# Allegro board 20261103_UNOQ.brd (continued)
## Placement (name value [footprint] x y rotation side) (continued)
R2645  0  [R0201_H030]  46.38 46.96 270 bottom
R2646  0  [R0201_H030]  20.19 4.31 90 bottom
R2660  220K  [R0201_H030]  33.71 57.35 90 top
R2661  220K  [R0201_H030]  32.61 57.35 270 top
R2664  220K  [R0201_H030]  43.45 60.86 0 top
R2665  220K  [R0201_H030]  44.25 60.86 0 top
R2666  2.2K  [R0201_H030]  33.53 13.54 270 bottom
R2667  2.2K  [R0201_H030]  35.57 13.54 270 bottom
R2668  0  [R0201_H030]  36.6 13.54 270 bottom
R2669  0  [R0201_H030]  34.55 13.54 270 bottom
R2670  0  [R0201_H030]  45.11 18.68 90 top
R2671  0  [R0201_H030]  45.14 18.14 90 top
R2701  10_1%  [R0402_H040]  21.85 8.44 180 top
R2702  10_1%  [R0402_H040]  20.89 8.47 180 top
R2703  10_1%  [R0402_H040]  19.95 8.47 180 top
R2704  10_1%  [R0402_H040]  17.21 8.46 180 top
R2705  10_1%  [R0402_H040]  18.08 8.47 180 top
R2706  10_1%  [R0402_H040]  7.87 8.24 180 top
R2707  10_1%  [R0402_H040]  11.34 8.24 180 top
R2708  10_1%  [R0402_H040]  10.48 8.26 180 top
R2709  10_1%  [R0402_H040]  9.55 8.26 180 top
R2710  10_1%  [R0402_H040]  8.69 8.25 180 top
R2711  10_1%  [R0402_H040]  19.03 8.47 180 top
R2712  1K  [R0201_H030]  42.2 32.8 180 bottom
R2713  1K  [R0201_H030]  45.4 33.4 90 bottom
R2714  1K  [R0201_H030]  41.5 34.2 180 bottom
R2715  1K  [R0201_H030]  40.1 35.4 90 bottom
R2716  1K  [R0201_H030]  39.1 31.6 180 bottom
R2717  1K  [R0201_H030]  41.6 31.7 180 bottom
R2723  4.7K  [R0402_H040]  46.56 5.34 0 bottom
R2724  15K_1%  [R0402_H040]  45.64 5.34 0 bottom
R2725  4.7K  [R0402_H040]  41.95 5.34 0 bottom
R2726  4.7K  [R0402_H040]  42.87 5.34 0 bottom
R2727  15K_1%  [R0402_H040]  44.72 5.34 0 bottom
R2728  4.7K  [R0402_H040]  43.8 5.34 0 bottom
R2729  4.7K  [R0402_H040]  39.11 5.76 0 bottom
R2730  15K_1%  [R0402_H040]  37.79 6.25 90 bottom
R2731  4.7K  [R0402_H040]  35.85 6.44 90 bottom
R2732  4.7K  [R0402_H040]  41.03 5.34 0 bottom
R2733  15K_1%  [R0402_H040]  40.18 5.84 0 bottom
R2734  4.7K  [R0402_H040]  39.7 4.43 90 bottom
R2735  330  [R0402_H040]  29.21 65.49 90 top
R2801  10K_1%  [R0201_H030]  11.94 40.04 90 bottom
R2802  499K_1%  [R0201_H030]  13.33 39.75 0 bottom
R2803  95.3K_1%  [R0201_H030]  12.83 39.75 180 bottom
R2804  10K_1%  [R0201_H030]  10.75 32.15 90 bottom
R2805  453K_1%  [R0201_H030]  11.6 31.18 0 bottom
R2806  100K  [R0201_H030]  11.98 32.07 90 bottom
R2807  0  [R1206_H080]  7.7 41.5 180 bottom
R2808  10K_1%  [R0201_H030]  15.37 42.32 90 bottom
R2809  10K_1%  [R0201_H030]  14.22 46.58 270 bottom
R2810  10K_1%  [R0201_H030]  17.19 41.62 0 bottom
R2811  301K_1%  [R0201_H030]  5.72 43.02 180 top
R2812  100K  [R0201_H030]  5.72 44.16 180 top
R2813  0  [R0201_H030]  9.2 45.16 270 top
R2814  100K  [R0201_H030]  6.92 45.23 270 top
R2815  19.1K_1%  [R0201_H030]  5.58 45.54 180 top
R2816  1K  [R0201_H030]  6.93 45.84 270 top
R2817  0  [R0603_H060]  8.9 31.84 90 bottom
R2901  0  [R0201_H030]  23.73 62.55 270 top
R2902  0  [R0201_H030]  3.78 60.94 90 top
R2903  0  [R0201_H030]  5.59 49.44 180 top
R2904  0  [R0201_H030]  4.38 63.34 90 top
R2905  0  [R0201_H030]  4.38 62.6 90 top
R2906  0  [R0201_H030]  4.65 60.65 180 top
R2908  0  [R0201_H030]  23.19 59.79 180 top
R2909  0  [R0201_H030]  3.28 61.77 90 top
R3001  1M  [R0201_H030]  33.83 49.61 0 top
R3002  1M  [R0201_H030]  34.8 49.86 90 top
R3003  0  [R0201_H030]  34.93 58.27 0 top
R3004  0  [R0201_H030]  36.79 57.76 180 top
R3005  0  [R0201_H030]  37.56 57.76 180 top
R3006  0  [R0201_H030]  38.77 59.19 270 top
R3007  1M  [R0201_H030]  33.07 53.8 0 top
R3009  0  [R0402_H040]  39.05 51.38 0 bottom
R3010  0  [R0402_H040]  33.64 46.39 270 top
R3011  0  [R0402_H040]  36.75 46.82 270 top
R3012  0  [R0402_H040]  36.87 50.75 90 bottom
R3013  0  [R0402_H040]  31.52 51.16 90 top
R3014  0  [R0201_H030]  34.67 43.78 90 top
R3015  0  [R0201_H030]  31.24 43.78 270 top
R3016  0  [R0201_H030]  37.14 43.17 180 top
R3017  0  [R0201_H030]  37.79 43.04 180 top
R3018  0  [R0201_H030]  36.55 43.34 180 top
R3019  39.2K_1%  [R0201_H030]  32.97 50.67 90 top
R3020  5.6K_1%  [R0201_H030]  32.97 51.21 270 top
R3022  2.2K  [R0201_H030]  35.85 52.15 90 bottom
R3023  2.2K  [R0201_H030]  38.96 54.61 270 top
R3024  10K_1%  [R0201_H030]  25.7 61.09 0 top
R3025  4.7K  [R0201_H030]  38.96 54.05 270 top
R3026  2.2K  [R0201_H030]  32.29 43.77 270 top
R3027  2.2K  [R0201_H030]  33.49 43.77 90 top
R3028  0  [R0201_H030]  35.37 41.73 270 top
RT701  NCP03WF104F05RL  [TRES0201_H030]  39.24 14.53 90 bottom
RT1901  NCP03WF104F05RL  [TRES0201_H030]  41.96 10.31 0 top
SB701  SB2P  [SB0201]  36.19 15.44 180 top
SB1001  SB2P  [SB0201]  30.75 20.04 90 top
SB1002  SB2P  [SB0201]  30.78 19.52 90 top
SB1003  SB2P  [SB0201]  29.99 17.62 90 top
SB1004  SB2P  [SB0201]  29.99 18.13 90 top
SB1701  SB2P  [SB0201]  26.99 29.02 0 top
SB1702  SB2P  [SB0201]  26.44 29.02 0 top
SB1801  SB2P  [SB0201]  26.75 38.85 0 top
SB1802  SB2P  [SB0201]  26.3 38.85 0 top
SB2801  SB2P  [SB0201#2]  11.97 39.19 90 bottom
SOC1  QRB-2210-0-NSP752-TR-00-0  [BGA752_120X124_0D4_H10]  29.77 34.28 90 top
TP601  TP  [TP20MIL]  38.94 8.88 0 top
TP602  TP  [TP20MIL]  38.23 8.85 0 top
TP701  TP  [TP20MIL]  31.4 12.87 0 top
TP702  TP  [TP20MIL]  29.34 11.65 0 top
TP703  TP  [TP20MIL]  39.66 8.85 0 top
TP704  TP  [TP20MIL]  37.62 9.87 0 top
TP705  TP  [TP20MIL]  30.09 14.96 0 top
TP706  TP  [TP20MIL]  35.79 9.22 0 top
TP1203  TP  [TP20MIL]  32.16 24.81 0 top
TP1204  TP  [TP20MIL]  32.16 25.61 0 top
TP1205  TP  [TP20MIL]  31.33 25.58 0 top
TP1206  TP  [TP20MIL]  31.33 24.78 0 top
TP1207  TP  [TP32MIL_OSP]  10.67 2.17 180 bottom
TP1208  TP  [TP32MIL_OSP]  12.67 2.17 180 bottom
TP1209  TP  [TP32MIL_OSP]  14.67 2.17 180 bottom
TP1210  TP  [TP32MIL_OSP]  16.67 2.17 180 bottom
TP1211  TP  [TP32MIL_OSP]  18.67 2.17 180 bottom
TP1212  TP  [TP32MIL_OSP]  20.67 2.17 180 bottom
TP1213  TP  [TP32MIL_OSP]  22.67 2.17 180 bottom
TP1301  TP  [TP20MIL]  35.26 23.17 0 top
TP1310  TP  [TP20MIL]  22.99 35.86 90 top
TP1311  TP  [TP20MIL]  22.45 33.93 90 top
TP1313  TP  [TP20MIL]  22.94 34.55 90 top
TP1314  TP  [TP20MIL]  22.52 35.24 90 top
TP1315  TP  [TP20MIL]  22.51 36.56 0 top
TP1501  TP  [TP20MIL]  30.04 25.32 0 top
TP1502  TP  [TP20MIL]  30.04 26.07 0 top
TP2501  TP  [TP20MIL]  17.4 26.67 0 bottom
TP2502  TP  [TP20MIL]  18.56 38.02 270 bottom
TP2503  TP  [TP20MIL]  17.4 25.91 0 bottom
TP2504  TP  [TP20MIL]  17.7 24.13 270 bottom
TP2506  TP  [TP20MIL]  7.41 23.08 270 bottom
TP2602  TP  [TP20MIL]  6.65 36.94 180 bottom
TP2603  TP  [TP20MIL]  6.31 42.62 180 bottom
TP2610  TP  [TP32MIL_OSP]  23.6 33.26 180 bottom
TP2611  TP  [TP32MIL_OSP]  51.5 55.75 180 bottom
TP2612  TP  [TP32MIL_OSP]  36.52 67.05 180 bottom
TP2613  TP  [TP32MIL_OSP]  38.52 67.05 180 bottom
TP2614  TP  [TP32MIL_OSP]  49.37 59.75 180 bottom
TP2615  TP  [TP40MIL]  49.37 55.75 180 bottom
TP2616  TP  [TP40MIL]  49.37 57.75 180 bottom
TP2617  TP  [TP32MIL_OSP]  51.5 59.75 180 bottom
TP2618  TP  [TP32MIL_OSP]  51.5 57.75 180 bottom
TP2901  TP  [TP20MIL]  4.31 51.11 0 top
TP3001  TP  [TP20MIL]  16.17 50.9 180 bottom
TP3002  TP  [TP20MIL]  35.55 43.82 0 top
TP3003  TP  [TP20MIL]  30.99 44.43 0 top
TP3004  TP  [TP20MIL]  37.58 56.91 0 top
TP3005  TP  [TP20MIL]  39.03 58.58 0 top
TP3006  TP  [TP20MIL]  38.53 55.32 0 top
TP3007  TP  [TP20MIL]  33.15 52.07 0 top
U1101  TXS0104ERUTR_QFN12P  [QFN12P_20X17_04_H060]  16.75 38.12 180 bottom
U1102  TXS0101DBVR_SOT23_6P  [SOT23_6P_29X28_H150]  17.09 32.69 90 bottom
U2501  74LVC1G3157DW-7_SOT363_6P  [SOT363_6P_21X20_H110]  44.71 44.01 270 bottom
U2601  RCLAMP0524PATCT  [DFN10P_25X10_05_H070_SE]  30.95 60.45 180 top
U2602  RCLAMP0524PATCT  [DFN10P_25X10_05_H070_SE]  36.73 59.33 270 top
U2604  RCLAMP3654PATCT_DFN6P  [DFN6P_16_PAD13X05_05H070P13X045]  40.64 58.45 90 top
U2605  RCLAMP0524PATCT  [DFN10P_25X10_05_H070_SE]  14.62 61.22 90 bottom
U2606  RCLAMP0524PATCT  [DFN10P_25X10_05_H070_SE]  33.63 52.68 270 bottom
U2607  RCLAMP0522P.TCT  [DFN6P_16X10_05_H070]  20.44 61.22 90 bottom
U2608  RCLAMP0524PATCT  [DFN10P_25X10_05_H070_SE]  26.05 62.12 90 bottom
U2609  RCLAMP0524PATCT  [DFN10P_25X10_05_H070_SE]  18.39 52.68 270 bottom
U2610  RCLAMP0524PATCT  [DFN10P_25X10_05_H070_SE]  26.01 52.68 270 bottom
U2611  RCLAMP0524PATCT  [DFN10P_25X10_05_H070_SE]  41.86 49.7 0 bottom
U2612  RCLAMP0524PATCT  [DFN10P_25X10_05_H070_SE]  41.3 52.58 270 bottom
U2801  TPS62A02APDDCR_SOT23_6P  [SOT23_6P_29X28_H110]  12.92 42.03 180 bottom
U2802  TPS62A02APDDCR_SOT23_6P  [SOT23_6P_29X28_H110]  11.74 34.1 180 bottom
U2803  LMR51440SDRRR_DFN12P  [DFN12_30_0D5_H08_P25X13_DRR]  8.05 43.04 0 top
U2901  WCBN3536A_MODULE51P  [MODULE51_160X120_1D1_H26_LITEON]  13.86 57.13 90 top
U3001  ANX7625BN-AC-R_BGA64P  [BGA64P_40_04_H090]  35.97 52.54 180 top
U3004  TPS7A2030PDBVR_SOT23_5P  [SOT23_5P_29X28_H150]  26.65 58.48 270 top
Y701  38.4M_X1.6X1.2  [XTAL4P_16X12_H070_TXC]  33.07 10.79 180 top
Y2501  16M_X3.2X2.5  [XTAL4P_32X25_H080]  10.36 17.19 270 bottom
Y2502  32.768K_X3.2X1.5  [XTAL2P_32X15_H090]  14.96 16.87 270 bottom
Y3001  27M_X3.2X2.5  [XTAL4P_32X25_H080_HOSONIC]  30.05 53.73 270 top

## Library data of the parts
ANT1 = CLIP2P
C501-C514 C601-C610 C701-C721 C801-C832 C901 C902 C1001-C1012 C1101-C1106 C1201-C1203 C1601-C1604 C1701-C1725 C1727-C1743 C1801-C1831 C1833-C1851 C1901-C1940 C2101-C2107 C2201-C2220 C2501-C2529 C2601-C2605 C2607-C2611 C2614-C2633 C2701-C2706 C2801-C2816 C2901 C2907 C2909 C2911 C2912 C2921-C2924 C3001-C3018 C3021 C3022 C3025-C3028 = CAP_NP
C3019 C3020 = CAP_NP: signal model: CAP_NP_78.10423.L15_C0201_H030__100NF/10V
D2801-D2803 = DIODE_SCHOTTKY
D26001-D26003 D26005-D26009 D26017 D26046-D26051 D26063-D26067 D26069-D26076 D26087-D26094 D26097 D26099-D26105 = DIODE_ESD_BI
D26201 = PJGBLC24C_SOD323FL
D27001-D27104 D27201 = LED
D27301 D27302 D27401 D27402 = LED4P_RED_BLU_GRN_A1
DRAM1 = MT53E512M32D1ZW-046_WT_B
EMMC1 = EMMC16G-MW28-GA01_BGA153P
F501 = BEAD
JANALOG1 = WTB14P_NP2P_0
JBTN1 = TS-A57AHNP-2-W-S085_SW5P
JCTL1 = HEAD2X5P
JDIGITAL1 = HEAD20P_1
JMEDIA1 JMISC1 = HEAD2X30P_F_R
JSPI1 = HEAD2X3P_M
JUSB1 = USB3-24CSW-R9H-H_USB2X12P
L601 L2801 L2802 = L
L1001-L1004 L2803 = CHOKE
MCU1 = STM32U585AII6TR_BGA169P_2
PMIC1 = PM-4125-3-NSP194-TR-01-0_11
Q2707-Q2709 = NPNX2_E2B2C1E1B1C2
Q2801 = PMOSFET_GSD
Q2802 = NPN_BEC
QWIIC1 = WTB4P_NP2P
R501-R503 R601 R603-R607 R701-R703 R705-R709 R901 R902 R1101 R1102 R1201-R1206 R1208 R1301-R1321 R1401 R1522 R1601 R1602 R2113 R2114 R2201 R2202 R2501-R2509 R2511-R2517 R2605-R2619 R2621-R2626 R2631-R2646 R2660 R2661 R2664-R2671 R2701-R2717 R2723-R2735 R2801-R2817 R2901-R2906 R2908 R2909 R3001-R3007 R3009-R3020 R3022-R3028 = RES
R1207 = RES: signal model: RES_63.22038.1F1_R0201_H030_22__22
R1501-R1510 = RES: signal model: RES_DNP_63.R0038.1F1_R0201_H030_0
RT701 RT1901 = TRES
SB701 SB1001-SB1004 SB1701 SB1702 SB1801 SB1802 SB2801 = SB2P
SOC1 = QRB-2210-0-NSP752-TR-00-0_43
TP601 TP602 TP701-TP706 TP1203-TP1213 TP1301 TP1310 TP1311 TP1313-TP1315 TP1501 TP1502 TP2501-TP2504 TP2506 TP2602 TP2603 TP2610-TP2618 TP2901 TP3001-TP3007 = TP
U1101 = TXS0104ERUTR_QFN12P
U1102 = TXS0101DBVR_SOT23_6P
U2501 = 74LVC1G3157DW-7_SOT363_1
U2601 U2602 U2605 U2606 U2608-U2612 = RCLAMP0524PATCT_DFN10P
U2604 = RCLAMP3654PATCT_DFN6P
U2607 = RCLAMP0522P.TCT_DFN6P
U2801 U2802 = TPS62A02APDDCR_SOT23_6P
U2803 = LMR51440SDRRR_DFN12P_1
U2901 = WCBN3536A_MODULE51P
U3001 = ANX7625BN-AC-R_BGA64P
U3004 = TPS7A2030PDBVR_SOT23_5P
Y701 = OW38470002_XTAL4P
Y2501 Y3001 = XTAL4P_P13
Y2502 = XTAL

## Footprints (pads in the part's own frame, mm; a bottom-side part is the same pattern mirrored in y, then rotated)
ANT2_1920X400_A
  rect 1x0.5 smd: 1(0,0)
  custom 1x1 smd: 2(-5.6,-0.25)
BEAD0402_H060
  rect 0.559x0.559 smd: 1(0,0.483) 2(0,-0.483)
BGA64P_40_04_H090
  round 0.25 smd: A1(1.4,-1.4) A2(1,-1.4) A3(0.6,-1.4) A4(0.2,-1.4) A5(-0.2,-1.4) A6(-0.6,-1.4) A7(-1,-1.4) A8(-1.4,-1.4) B1(1.4,-1) B2(1,-1) B3(0.6,-1) B4(0.2,-1) B5(-0.2,-1) B6(-0.6,-1) B7(-1,-1) B8(-1.4,-1) C1(1.4,-0.6) C2(1,-0.6) C3(0.6,-0.6) C4(0.2,-0.6) C5(-0.2,-0.6) C6(-0.6,-0.6) C7(-1,-0.6) C8(-1.4,-0.6) D1(1.4,-0.2) D2(1,-0.2) D3(0.6,-0.2) D4(0.2,-0.2) D5(-0.2,-0.2) D6(-0.6,-0.2) D7(-1,-0.2) D8(-1.4,-0.2) E1(1.4,0.2) E2(1,0.2) E3(0.6,0.2) E4(0.2,0.2) E5(-0.2,0.2) E6(-0.6,0.2) E7(-1,0.2) E8(-1.4,0.2) F1(1.4,0.6) F2(1,0.6) F3(0.6,0.6) F4(0.2,0.6) F5(-0.2,0.6) F6(-0.6,0.6) F7(-1,0.6) F8(-1.4,0.6) G1(1.4,1) G2(1,1) G3(0.6,1) G4(0.2,1) G5(-0.2,1) G6(-0.6,1) G7(-1,1) G8(-1.4,1) H1(1.4,1.4) H2(1,1.4) H3(0.6,1.4) H4(0.2,1.4) H5(-0.2,1.4) H6(-0.6,1.4) H7(-1,1.4) H8(-1.4,1.4)
BGA153P_130X115_05_H090
  round 0.25 smd: A1(3.25,-3.25) A2(2.75,-3.25) A3(2.25,-3.25) A4(1.75,-3.25) A5(1.25,-3.25) A6(0.75,-3.25) A7(0.25,-3.25) A8(-0.25,-3.25) A9(-0.75,-3.25) A10(-1.25,-3.25) A11(-1.75,-3.25) A12(-2.25,-3.25) A13(-2.75,-3.25) A14(-3.25,-3.25) B1(3.25,-2.75) B2(2.75,-2.75) B3(2.25,-2.75) B4(1.75,-2.75) B5(1.25,-2.75) B6(0.75,-2.75) B7(0.25,-2.75) B8(-0.25,-2.75) B9(-0.75,-2.75) B10(-1.25,-2.75) B11(-1.75,-2.75) B12(-2.25,-2.75) B13(-2.75,-2.75) B14(-3.25,-2.75) C1(3.25,-2.25) C2(2.75,-2.25) C3(2.25,-2.25) C4(1.75,-2.25) C5(1.25,-2.25) C6(0.75,-2.25) C7(0.25,-2.25) C8(-0.25,-2.25) C9(-0.75,-2.25) C10(-1.25,-2.25) C11(-1.75,-2.25) C12(-2.25,-2.25) C13(-2.75,-2.25) C14(-3.25,-2.25) D1(3.25,-1.75) D2(2.75,-1.75) D3(2.25,-1.75) D4(1.75,-1.75) D12(-2.25,-1.75) D13(-2.75,-1.75) D14(-3.25,-1.75) E1(3.25,-1.25) E2(2.75,-1.25) E3(2.25,-1.25) E5(1.25,-1.25) E6(0.75,-1.25) E7(0.25,-1.25) E8(-0.25,-1.25) E9(-0.75,-1.25) E10(-1.25,-1.25) E12(-2.25,-1.25) E13(-2.75,-1.25) E14(-3.25,-1.25) F1(3.25,-0.75) F2(2.75,-0.75) F3(2.25,-0.75) F5(1.25,-0.75) F10(-1.25,-0.75) F12(-2.25,-0.75) F13(-2.75,-0.75) F14(-3.25,-0.75) G1(3.25,-0.25) G2(2.75,-0.25) G3(2.25,-0.25) G5(1.25,-0.25) G10(-1.25,-0.25) G12(-2.25,-0.25) G13(-2.75,-0.25) G14(-3.25,-0.25) H1(3.25,0.25) H2(2.75,0.25) H3(2.25,0.25) H5(1.25,0.25) H10(-1.25,0.25) H12(-2.25,0.25) H13(-2.75,0.25) H14(-3.25,0.25) J1(3.25,0.75) J2(2.75,0.75) J3(2.25,0.75) J5(1.25,0.75) J10(-1.25,0.75) J12(-2.25,0.75) J13(-2.75,0.75) J14(-3.25,0.75) K1(3.25,1.25) K2(2.75,1.25) K3(2.25,1.25) K5(1.25,1.25) K6(0.75,1.25) K7(0.25,1.25) K8(-0.25,1.25) K9(-0.75,1.25) K10(-1.25,1.25) K12(-2.25,1.25) K13(-2.75,1.25) K14(-3.25,1.25) L1(3.25,1.75) L2(2.75,1.75) L3(2.25,1.75) L12(-2.25,1.75) L13(-2.75,1.75) L14(-3.25,1.75) M1(3.25,2.25) M2(2.75,2.25) M3(2.25,2.25) M4(1.75,2.25) M5(1.25,2.25) M6(0.75,2.25) M7(0.25,2.25) M8(-0.25,2.25) M9(-0.75,2.25) M10(-1.25,2.25) M11(-1.75,2.25) M12(-2.25,2.25) M13(-2.75,2.25) M14(-3.25,2.25) N1(3.25,2.75) N2(2.75,2.75) N3(2.25,2.75) N4(1.75,2.75) N5(1.25,2.75) N6(0.75,2.75) N7(0.25,2.75) N8(-0.25,2.75) N9(-0.75,2.75) N10(-1.25,2.75) N11(-1.75,2.75) N12(-2.25,2.75) N13(-2.75,2.75) N14(-3.25,2.75) P1(3.25,3.25) P2(2.75,3.25) P3(2.25,3.25) P4(1.75,3.25) P5(1.25,3.25) P6(0.75,3.25) P7(0.25,3.25) P8(-0.25,3.25) P9(-0.75,3.25) P10(-1.25,3.25) P11(-1.75,3.25) P12(-2.25,3.25) P13(-2.75,3.25) P14(-3.25,3.25)
BGA169_70_0D5_H06
  round 0.25 smd: A1(3,-3) A2(2.5,-3) A3(2,-3) A4(1.5,-3) A5(1,-3) A6(0.5,-3) A7(0,-3) A8(-0.5,-3) A9(-1,-3) A10(-1.5,-3) A11(-2,-3) A12(-2.5,-3) A13(-3,-3) B1(3,-2.5) B2(2.5,-2.5) B3(2,-2.5) B4(1.5,-2.5) B5(1,-2.5) B6(0.5,-2.5) B7(0,-2.5) B8(-0.5,-2.5) B9(-1,-2.5) B10(-1.5,-2.5) B11(-2,-2.5) B12(-2.5,-2.5) B13(-3,-2.5) C1(3,-2) C2(2.5,-2) C3(2,-2) C4(1.5,-2) C5(1,-2) C6(0.5,-2) C7(0,-2) C8(-0.5,-2) C9(-1,-2) C10(-1.5,-2) C11(-2,-2) C12(-2.5,-2) C13(-3,-2) D1(3,-1.5) D2(2.5,-1.5) D3(2,-1.5) D4(1.5,-1.5) D5(1,-1.5) D6(0.5,-1.5) D7(0,-1.5) D8(-0.5,-1.5) D9(-1,-1.5) D10(-1.5,-1.5) D11(-2,-1.5) D12(-2.5,-1.5) D13(-3,-1.5) E1(3,-1) E2(2.5,-1) E3(2,-1) E4(1.5,-1) E5(1,-1) E6(0.5,-1) E7(0,-1) E8(-0.5,-1) E9(-1,-1) E10(-1.5,-1) E11(-2,-1) E12(-2.5,-1) E13(-3,-1) F1(3,-0.5) F2(2.5,-0.5) F3(2,-0.5) F4(1.5,-0.5) F5(1,-0.5) F6(0.5,-0.5) F7(0,-0.5) F8(-0.5,-0.5) F9(-1,-0.5) F10(-1.5,-0.5) F11(-2,-0.5) F12(-2.5,-0.5) F13(-3,-0.5) G1(3,0) G2(2.5,0) G3(2,0) G4(1.5,0) G5(1,0) G6(0.5,0) G7(0,0) G8(-0.5,0) G9(-1,0) G10(-1.5,0) G11(-2,0) G12(-2.5,0) G13(-3,0) H1(3,0.5) H2(2.5,0.5) H3(2,0.5) H4(1.5,0.5) H5(1,0.5) H6(0.5,0.5) H7(0,0.5) H8(-0.5,0.5) H9(-1,0.5) H10(-1.5,0.5) H11(-2,0.5) H12(-2.5,0.5) H13(-3,0.5) J1(3,1) J2(2.5,1) J3(2,1) J4(1.5,1) J5(1,1) J6(0.5,1) J7(0,1) J8(-0.5,1) J9(-1,1) J10(-1.5,1) J11(-2,1) J12(-2.5,1) J13(-3,1) K1(3,1.5) K2(2.5,1.5) K3(2,1.5) K4(1.5,1.5) K5(1,1.5) K6(0.5,1.5) K7(0,1.5) K8(-0.5,1.5) K9(-1,1.5) K10(-1.5,1.5) K11(-2,1.5) K12(-2.5,1.5) K13(-3,1.5) L1(3,2) L2(2.5,2) L3(2,2) L4(1.5,2) L5(1,2) L6(0.5,2) L7(0,2) L8(-0.5,2) L9(-1,2) L10(-1.5,2) L11(-2,2) L12(-2.5,2) L13(-3,2) M1(3,2.5) M2(2.5,2.5) M3(2,2.5) M4(1.5,2.5) M5(1,2.5) M6(0.5,2.5) M7(0,2.5) M8(-0.5,2.5) M9(-1,2.5) M10(-1.5,2.5) M11(-2,2.5) M12(-2.5,2.5) M13(-3,2.5) N1(3,3) N2(2.5,3) N3(2,3) N4(1.5,3) N5(1,3) N6(0.5,3) N7(0,3) N8(-0.5,3) N9(-1,3) N10(-1.5,3) N11(-2,3) N12(-2.5,3) N13(-3,3)
BGA194_67X83_0D566_H10_QUALCOMM
  round 0.25 smd: A1(3.679,-2.689) A3(3.113,-2.689) A5(2.547,-2.689) A7(1.981,-2.689) A11(0.849,-2.689) A13(0.283,-2.689) A15(-0.283,-2.689) A17(-0.849,-2.689) A19(-1.415,-2.689) A21(-1.981,-2.689) A23(-2.547,-2.689) A25(-3.113,-2.689) A27(-3.679,-2.689) B2(3.396,-2.405) B4(2.83,-2.405) B6(2.264,-2.405) B8(1.698,-2.405) B12(0.566,-2.405) B14(0,-2.405) B16(-0.566,-2.405) B18(-1.132,-2.405) B22(-2.264,-2.405) B24(-2.83,-2.405) B26(-3.396,-2.405) C1(3.679,-2.122) C3(3.113,-2.122) C5(2.547,-2.122) C7(1.981,-2.122) C11(0.849,-2.122) C13(0.283,-2.122) C17(-0.849,-2.122) C19(-1.415,-2.122) C21(-1.981,-2.122) C23(-2.547,-2.122) C25(-3.113,-2.122) C27(-3.679,-2.122) D2(3.396,-1.839) D4(2.83,-1.839) D6(2.264,-1.839) D8(1.698,-1.839) D10(1.132,-1.839) D12(0.566,-1.839) D22(-2.264,-1.839) D24(-2.83,-1.839) D26(-3.396,-1.839) E1(3.679,-1.556) E3(3.113,-1.556) E5(2.547,-1.556) E7(1.981,-1.556) E9(1.415,-1.556) E11(0.849,-1.556) E15(-0.283,-1.556) E19(-1.415,-1.556) E21(-1.981,-1.556) E23(-2.547,-1.556) E27(-3.679,-1.556) F2(3.396,-1.274) F4(2.83,-1.274) F6(2.264,-1.274) F8(1.698,-1.274) F10(1.132,-1.274) F14(0,-1.274) F16(-0.566,-1.274) F22(-2.264,-1.274) F26(-3.396,-1.274) G1(3.679,-0.991) G3(3.113,-0.991) G5(2.547,-0.991) G7(1.981,-0.991) G11(0.849,-0.991) G15(-0.283,-0.991) G17(-0.849,-0.991) G23(-2.547,-0.991) G25(-3.113,-0.991) G27(-3.679,-0.991) H6(2.264,-0.707) H8(1.698,-0.707) H12(0.566,-0.707) H16(-0.566,-0.707) H20(-1.698,-0.707) H22(-2.264,-0.707) J5(2.547,-0.424) J13(0.283,-0.424) J15(-0.283,-0.424) J17(-0.849,-0.424) J19(-1.415,-0.424) J21(-1.981,-0.424) J23(-2.547,-0.424) J25(-3.113,-0.424) J27(-3.679,-0.424) K4(2.83,-0.141) K6(2.264,-0.141) K8(1.698,-0.141) K10(1.132,-0.141) K12(0.566,-0.141) K14(0,-0.141) K16(-0.566,-0.141) K18(-1.132,-0.141) K20(-1.698,-0.141) K22(-2.264,-0.141) K24(-2.83,-0.141) K26(-3.396,-0.141) L3(3.113,0.141) L5(2.547,0.141) L7(1.981,0.141) L13(0.283,0.141) L15(-0.283,0.141) L17(-0.849,0.141) L19(-1.415,0.141) L21(-1.981,0.141) L27(-3.679,0.141) M2(3.396,0.424) M6(2.264,0.424) M10(1.132,0.424) M12(0.566,0.424) M14(0,0.424) M16(-0.566,0.424) M18(-1.132,0.424) M20(-1.698,0.424) M22(-2.264,0.424) M24(-2.83,0.424) N3(3.113,0.707) N5(2.547,0.707) N7(1.981,0.707) N9(1.415,0.707) N13(0.283,0.707) N17(-0.849,0.707) N21(-1.981,0.707) N23(-2.547,0.707) N27(-3.679,0.707) P2(3.396,0.991) P4(2.83,0.991) P8(1.698,0.991) P10(1.132,0.991) P12(0.566,0.991) P18(-1.132,0.991) P22(-2.264,0.991) P24(-2.83,0.991) P26(-3.396,0.991) R1(3.679,1.274) R5(2.547,1.274) R7(1.981,1.274) R9(1.415,1.274) R11(0.849,1.274) R15(-0.283,1.274) R19(-1.415,1.274) R21(-1.981,1.274) R23(-2.547,1.274) R25(-3.113,1.274) R27(-3.679,1.274) T4(2.83,1.556) T6(2.264,1.556) T8(1.698,1.556) T10(1.132,1.556) T20(-1.698,1.556) T22(-2.264,1.556) T24(-2.83,1.556) U3(3.113,1.839) U5(2.547,1.839) U7(1.981,1.839) U13(0.283,1.839) U19(-1.415,1.839) U25(-3.113,1.839) V2(3.396,2.122) V4(2.83,2.122) V6(2.264,2.122) V8(1.698,2.122) V10(1.132,2.122) V12(0.566,2.122) V16(-0.566,2.122) V18(-1.132,2.122) V22(-2.264,2.122) V24(-2.83,2.122) V26(-3.396,2.122) W1(3.679,2.405) W3(3.113,2.405) W5(2.547,2.405) W7(1.981,2.405) W13(0.283,2.405) W15(-0.283,2.405) W21(-1.981,2.405) W23(-2.547,2.405) W25(-3.113,2.405) W27(-3.679,2.405) Y2(3.396,2.689) Y4(2.83,2.689) Y10(1.132,2.689) Y12(0.566,2.689) Y14(0,2.689) Y16(-0.566,2.689) Y18(-1.132,2.689) Y20(-1.698,2.689) Y22(-2.264,2.689) Y26(-3.396,2.689)
BGA200P_145X100_H110
  round 0.325 smd: A1(4.4,-6.825) A2(3.6,-6.825) A3(2.8,-6.825) A4(2,-6.825) A5(1.2,-6.825) A8(-1.2,-6.825) A9(-2,-6.825) A10(-2.8,-6.825) A11(-3.6,-6.825) A12(-4.4,-6.825) AA1(4.4,6.175) AA2(3.6,6.175) AA3(2.8,6.175) AA4(2,6.175) AA5(1.2,6.175) AA8(-1.2,6.175) AA9(-2,6.175) AA10(-2.8,6.175) AA11(-3.6,6.175) AA12(-4.4,6.175) AB1(4.4,6.825) AB2(3.6,6.825) AB3(2.8,6.825) AB4(2,6.825) AB5(1.2,6.825) AB8(-1.2,6.825) AB9(-2,6.825) AB10(-2.8,6.825) AB11(-3.6,6.825) AB12(-4.4,6.825) B1(4.4,-6.175) B2(3.6,-6.175) B3(2.8,-6.175) B4(2,-6.175) B5(1.2,-6.175) B8(-1.2,-6.175) B9(-2,-6.175) B10(-2.8,-6.175) B11(-3.6,-6.175) B12(-4.4,-6.175) C1(4.4,-5.525) C2(3.6,-5.525) C3(2.8,-5.525) C4(2,-5.525) C5(1.2,-5.525) C8(-1.2,-5.525) C9(-2,-5.525) C10(-2.8,-5.525) C11(-3.6,-5.525) C12(-4.4,-5.525) D1(4.4,-4.875) D2(3.6,-4.875) D3(2.8,-4.875) D4(2,-4.875) D5(1.2,-4.875) D8(-1.2,-4.875) D9(-2,-4.875) D10(-2.8,-4.875) D11(-3.6,-4.875) D12(-4.4,-4.875) E1(4.4,-4.225) E2(3.6,-4.225) E3(2.8,-4.225) E4(2,-4.225) E5(1.2,-4.225) E8(-1.2,-4.225) E9(-2,-4.225) E10(-2.8,-4.225) E11(-3.6,-4.225) E12(-4.4,-4.225) F1(4.4,-3.575) F2(3.6,-3.575) F3(2.8,-3.575) F4(2,-3.575) F5(1.2,-3.575) F8(-1.2,-3.575) F9(-2,-3.575) F10(-2.8,-3.575) F11(-3.6,-3.575) F12(-4.4,-3.575) G1(4.4,-2.925) G2(3.6,-2.925) G3(2.8,-2.925) G4(2,-2.925) G5(1.2,-2.925) G8(-1.2,-2.925) G9(-2,-2.925) G10(-2.8,-2.925) G11(-3.6,-2.925) G12(-4.4,-2.925) H1(4.4,-2.275) H2(3.6,-2.275) H3(2.8,-2.275) H4(2,-2.275) H5(1.2,-2.275) H8(-1.2,-2.275) H9(-2,-2.275) H10(-2.8,-2.275) H11(-3.6,-2.275) H12(-4.4,-2.275) J1(4.4,-1.625) J2(3.6,-1.625) J3(2.8,-1.625) J4(2,-1.625) J5(1.2,-1.625) J8(-1.2,-1.625) J9(-2,-1.625) J10(-2.8,-1.625) J11(-3.6,-1.625) J12(-4.4,-1.625) K1(4.4,-0.975) K2(3.6,-0.975) K3(2.8,-0.975) K4(2,-0.975) K5(1.2,-0.975) K8(-1.2,-0.975) K9(-2,-0.975) K10(-2.8,-0.975) K11(-3.6,-0.975) K12(-4.4,-0.975) N1(4.4,0.975) N2(3.6,0.975) N3(2.8,0.975) N4(2,0.975) N5(1.2,0.975) N8(-1.2,0.975) N9(-2,0.975) N10(-2.8,0.975) N11(-3.6,0.975) N12(-4.4,0.975) P1(4.4,1.625) P2(3.6,1.625) P3(2.8,1.625) P4(2,1.625) P5(1.2,1.625) P8(-1.2,1.625) P9(-2,1.625) P10(-2.8,1.625) P11(-3.6,1.625) P12(-4.4,1.625) R1(4.4,2.275) R2(3.6,2.275) R3(2.8,2.275) R4(2,2.275) R5(1.2,2.275) R8(-1.2,2.275) R9(-2,2.275) R10(-2.8,2.275) R11(-3.6,2.275) R12(-4.4,2.275) T1(4.4,2.925) T2(3.6,2.925) T3(2.8,2.925) T4(2,2.925) T5(1.2,2.925) T8(-1.2,2.925) T9(-2,2.925) T10(-2.8,2.925) T11(-3.6,2.925) T12(-4.4,2.925) U1(4.4,3.575) U2(3.6,3.575) U3(2.8,3.575) U4(2,3.575) U5(1.2,3.575) U8(-1.2,3.575) U9(-2,3.575) U10(-2.8,3.575) U11(-3.6,3.575) U12(-4.4,3.575) V1(4.4,4.225) V2(3.6,4.225) V3(2.8,4.225) V4(2,4.225) V5(1.2,4.225) V8(-1.2,4.225) V9(-2,4.225) V10(-2.8,4.225) V11(-3.6,4.225) V12(-4.4,4.225) W1(4.4,4.875) W2(3.6,4.875) W3(2.8,4.875) W4(2,4.875) W5(1.2,4.875) W8(-1.2,4.875) W9(-2,4.875) W10(-2.8,4.875) W11(-3.6,4.875) W12(-4.4,4.875) Y1(4.4,5.525) Y2(3.6,5.525) Y3(2.8,5.525) Y4(2,5.525) Y5(1.2,5.525) Y8(-1.2,5.525) Y9(-2,5.525) Y10(-2.8,5.525) Y11(-3.6,5.525) Y12(-4.4,5.525)
BGA752_120X124_0D4_H10
  round 0.25 smd: A1(5.8,-5.6) A2(5.4,-5.6) A3(5,-5.6) A4(4.6,-5.6) A5(4.2,-5.6) A7(3.4,-5.6) A8(3,-5.6) A10(2.2,-5.6) A11(1.8,-5.6) A13(1,-5.6) A14(0.6,-5.6) A15(0.2,-5.6) A16(-0.2,-5.6) A17(-0.6,-5.6) A19(-1.4,-5.6) A20(-1.8,-5.6) A22(-2.6,-5.6) A23(-3,-5.6) A25(-3.8,-5.6) A26(-4.2,-5.6) A27(-4.6,-5.6) A28(-5,-5.6) A29(-5.4,-5.6) A30(-5.8,-5.6) AA1(5.8,2.4) AA2(5.4,2.4) AA3(5,2.4) AA4(4.6,2.4) AA5(4.2,2.4) AA6(3.8,2.4) AA7(3.4,2.4) AA8(3,2.4) AA9(2.6,2.4) AA11(1.8,2.4) AA12(1.4,2.4) AA14(0.6,2.4) AA16(-0.2,2.4) AA17(-0.6,2.4) AA18(-1,2.4) AA19(-1.4,2.4) AA20(-1.8,2.4) AA21(-2.2,2.4) AA22(-2.6,2.4) AA23(-3,2.4) AA24(-3.4,2.4) AA25(-3.8,2.4) AA26(-4.2,2.4) AA27(-4.6,2.4) AA28(-5,2.4) AA29(-5.4,2.4) AA30(-5.8,2.4) AB1(5.8,2.8) AB2(5.4,2.8) AB3(5,2.8) AB4(4.6,2.8) AB5(4.2,2.8) AB7(3.4,2.8) AB8(3,2.8) AB9(2.6,2.8) AB10(2.2,2.8) AB11(1.8,2.8) AB12(1.4,2.8) AB13(1,2.8) AB14(0.6,2.8) AB20(-1.8,2.8) AB21(-2.2,2.8) AB22(-2.6,2.8) AB23(-3,2.8) AB24(-3.4,2.8) AB25(-3.8,2.8) AB26(-4.2,2.8) AB27(-4.6,2.8) AB28(-5,2.8) AB29(-5.4,2.8) AB30(-5.8,2.8) AC2(5.4,3.2) AC3(5,3.2) AC4(4.6,3.2) AC5(4.2,3.2) AC6(3.8,3.2) AC7(3.4,3.2) AC8(3,3.2) AC9(2.6,3.2) AC10(2.2,3.2) AC11(1.8,3.2) AC12(1.4,3.2) AC13(1,3.2) AC14(0.6,3.2) AC15(0.2,3.2) AC16(-0.2,3.2) AC17(-0.6,3.2) AC18(-1,3.2) AC20(-1.8,3.2) AC21(-2.2,3.2) AC22(-2.6,3.2) AC23(-3,3.2) AC24(-3.4,3.2) AC25(-3.8,3.2) AC26(-4.2,3.2) AC27(-4.6,3.2) AC28(-5,3.2) AC29(-5.4,3.2) AD1(5.8,3.6) AD2(5.4,3.6) AD3(5,3.6) AD4(4.6,3.6) AD5(4.2,3.6) AD6(3.8,3.6) AD7(3.4,3.6) AD8(3,3.6) AD9(2.6,3.6) AD10(2.2,3.6) AD11(1.8,3.6) AD12(1.4,3.6) AD13(1,3.6) AD14(0.6,3.6) AD15(0.2,3.6) AD17(-0.6,3.6) AD18(-1,3.6) AD19(-1.4,3.6) AD27(-4.6,3.6) AD28(-5,3.6) AD29(-5.4,3.6) AD30(-5.8,3.6) AE1(5.8,4) AE2(5.4,4) AE3(5,4) AE4(4.6,4) AE5(4.2,4) AE6(3.8,4) AE7(3.4,4) AE8(3,4) AE9(2.6,4) AE10(2.2,4) AE11(1.8,4) AE12(1.4,4) AE13(1,4) AE14(0.6,4) AE15(0.2,4) AE17(-0.6,4) AE18(-1,4) AE19(-1.4,4) AE20(-1.8,4) AE21(-2.2,4) AE22(-2.6,4) AE23(-3,4) AE24(-3.4,4) AE25(-3.8,4) AE26(-4.2,4) AE27(-4.6,4) AE28(-5,4) AE29(-5.4,4) AE30(-5.8,4) AF2(5.4,4.4) AF3(5,4.4) AF4(4.6,4.4) AF5(4.2,4.4) AF6(3.8,4.4) AF7(3.4,4.4) AF8(3,4.4) AF9(2.6,4.4) AF10(2.2,4.4) AF11(1.8,4.4) AF12(1.4,4.4) AF13(1,4.4) AF14(0.6,4.4) AF15(0.2,4.4) AF16(-0.2,4.4) AF17(-0.6,4.4) AF18(-1,4.4) AF19(-1.4,4.4) AF20(-1.8,4.4) AF21(-2.2,4.4) AF22(-2.6,4.4) AF23(-3,4.4) AF24(-3.4,4.4) AF25(-3.8,4.4) AF26(-4.2,4.4) AF27(-4.6,4.4) AF28(-5,4.4) AF29(-5.4,4.4) AG1(5.8,4.8) AG2(5.4,4.8) AG3(5,4.8) AG4(4.6,4.8) AG5(4.2,4.8) AG6(3.8,4.8) AG7(3.4,4.8) AG8(3,4.8) AG9(2.6,4.8) AG10(2.2,4.8) AG11(1.8,4.8) AG12(1.4,4.8) AG13(1,4.8) AG14(0.6,4.8) AG15(0.2,4.8) AG16(-0.2,4.8) AG17(-0.6,4.8) AG18(-1,4.8) AG19(-1.4,4.8) AG20(-1.8,4.8) AG21(-2.2,4.8) AG22(-2.6,4.8) AG23(-3,4.8) AG24(-3.4,4.8) AG25(-3.8,4.8) AG26(-4.2,4.8) AG27(-4.6,4.8) AG28(-5,4.8) AG29(-5.4,4.8) AG30(-5.8,4.8) AH1(5.8,5.2) AH2(5.4,5.2) AH3(5,5.2) AH4(4.6,5.2) AH5(4.2,5.2) AH6(3.8,5.2) AH7(3.4,5.2) AH8(3,5.2) AH9(2.6,5.2) AH10(2.2,5.2) AH11(1.8,5.2) AH12(1.4,5.2) AH13(1,5.2) AH14(0.6,5.2) AH15(0.2,5.2) AH16(-0.2,5.2) AH17(-0.6,5.2) AH18(-1,5.2) AH19(-1.4,5.2) AH20(-1.8,5.2) AH21(-2.2,5.2) AH22(-2.6,5.2) AH23(-3,5.2) AH24(-3.4,5.2) AH25(-3.8,5.2) AH26(-4.2,5.2) AH27(-4.6,5.2) AH28(-5,5.2) AH29(-5.4,5.2) AH30(-5.8,5.2) AJ1(5.8,5.6) AJ2(5.4,5.6) AJ4(4.6,5.6) AJ5(4.2,5.6) AJ7(3.4,5.6) AJ8(3,5.6) AJ10(2.2,5.6) AJ11(1.8,5.6) AJ13(1,5.6) AJ14(0.6,5.6) AJ16(-0.2,5.6) AJ17(-0.6,5.6) AJ19(-1.4,5.6) AJ20(-1.8,5.6) AJ22(-2.6,5.6) AJ23(-3,5.6) AJ25(-3.8,5.6) AJ26(-4.2,5.6) AJ28(-5,5.6) AJ29(-5.4,5.6) AJ30(-5.8,5.6) B1(5.8,-5.2) B2(5.4,-5.2) B3(5,-5.2) B4(4.6,-5.2) B5(4.2,-5.2) B6(3.8,-5.2) B7(3.4,-5.2) B8(3,-5.2) B9(2.6,-5.2) B10(2.2,-5.2) B11(1.8,-5.2) B12(1.4,-5.2) B13(1,-5.2) B14(0.6,-5.2) B15(0.2,-5.2) B16(-0.2,-5.2) B17(-0.6,-5.2) B18(-1,-5.2) B19(-1.4,-5.2) B20(-1.8,-5.2) B21(-2.2,-5.2) B22(-2.6,-5.2) B23(-3,-5.2) B24(-3.4,-5.2) B25(-3.8,-5.2) B26(-4.2,-5.2) B27(-4.6,-5.2) B28(-5,-5.2) B29(-5.4,-5.2) B30(-5.8,-5.2) C1(5.8,-4.8) C2(5.4,-4.8) C3(5,-4.8) C4(4.6,-4.8) C5(4.2,-4.8) C6(3.8,-4.8) C7(3.4,-4.8) C8(3,-4.8) C9(2.6,-4.8) C10(2.2,-4.8) C11(1.8,-4.8) C12(1.4,-4.8) C13(1,-4.8) C14(0.6,-4.8) C15(0.2,-4.8) C16(-0.2,-4.8) C17(-0.6,-4.8) C18(-1,-4.8) C19(-1.4,-4.8) C20(-1.8,-4.8) C21(-2.2,-4.8) C22(-2.6,-4.8) C23(-3,-4.8) C24(-3.4,-4.8) C25(-3.8,-4.8) C26(-4.2,-4.8) C27(-4.6,-4.8) C28(-5,-4.8) C29(-5.4,-4.8) C30(-5.8,-4.8) D1(5.8,-4.4) D2(5.4,-4.4) D3(5,-4.4) D4(4.6,-4.4) D5(4.2,-4.4) D6(3.8,-4.4) D7(3.4,-4.4) D8(3,-4.4) D9(2.6,-4.4) D10(2.2,-4.4) D11(1.8,-4.4) D12(1.4,-4.4) D13(1,-4.4) D14(0.6,-4.4) D15(0.2,-4.4) D16(-0.2,-4.4) D17(-0.6,-4.4) D18(-1,-4.4) D19(-1.4,-4.4) D20(-1.8,-4.4) D21(-2.2,-4.4) D22(-2.6,-4.4) D23(-3,-4.4) D24(-3.4,-4.4) D25(-3.8,-4.4) D26(-4.2,-4.4) D27(-4.6,-4.4) D28(-5,-4.4) D29(-5.4,-4.4) D30(-5.8,-4.4) E1(5.8,-4) E2(5.4,-4) E3(5,-4) E4(4.6,-4) E5(4.2,-4) E6(3.8,-4) E7(3.4,-4) E8(3,-4) E9(2.6,-4) E10(2.2,-4) E11(1.8,-4) E12(1.4,-4) E13(1,-4) E14(0.6,-4) E15(0.2,-4) E16(-0.2,-4) E17(-0.6,-4) E18(-1,-4) E19(-1.4,-4) E20(-1.8,-4) E21(-2.2,-4) E22(-2.6,-4) E23(-3,-4) E24(-3.4,-4) E25(-3.8,-4) E26(-4.2,-4) E27(-4.6,-4) E29(-5.4,-4) F1(5.8,-3.6) F2(5.4,-3.6) F3(5,-3.6) F4(4.6,-3.6) F5(4.2,-3.6) F6(3.8,-3.6) F7(3.4,-3.6) F8(3,-3.6) F9(2.6,-3.6) F10(2.2,-3.6) F11(1.8,-3.6) F12(1.4,-3.6) F13(1,-3.6) F14(0.6,-3.6) F15(0.2,-3.6) F16(-0.2,-3.6) F17(-0.6,-3.6) F18(-1,-3.6) F19(-1.4,-3.6) F20(-1.8,-3.6) F21(-2.2,-3.6) F22(-2.6,-3.6) F23(-3,-3.6) F24(-3.4,-3.6) F25(-3.8,-3.6) F26(-4.2,-3.6) F27(-4.6,-3.6) F28(-5,-3.6) F29(-5.4,-3.6) F30(-5.8,-3.6) G1(5.8,-3.2) G2(5.4,-3.2) G3(5,-3.2) G4(4.6,-3.2) G5(4.2,-3.2) G6(3.8,-3.2) G8(3,-3.2) G9(2.6,-3.2) G10(2.2,-3.2) G11(1.8,-3.2) G12(1.4,-3.2) G13(1,-3.2) G14(0.6,-3.2) G15(0.2,-3.2) G16(-0.2,-3.2) G17(-0.6,-3.2) G18(-1,-3.2) G19(-1.4,-3.2) G20(-1.8,-3.2) G21(-2.2,-3.2) G22(-2.6,-3.2) G23(-3,-3.2) G24(-3.4,-3.2) G25(-3.8,-3.2) G26(-4.2,-3.2) G27(-4.6,-3.2) G28(-5,-3.2) G29(-5.4,-3.2) G30(-5.8,-3.2) H1(5.8,-2.8) H2(5.4,-2.8) H3(5,-2.8) H4(4.6,-2.8) H5(4.2,-2.8) H6(3.8,-2.8) H7(3.4,-2.8) H9(2.6,-2.8) H11(1.8,-2.8) H13(1,-2.8) H15(0.2,-2.8) H18(-1,-2.8) H20(-1.8,-2.8) H22(-2.6,-2.8) H24(-3.4,-2.8) H25(-3.8,-2.8) H26(-4.2,-2.8) H27(-4.6,-2.8) H28(-5,-2.8) H29(-5.4,-2.8) J1(5.8,-2.4) J2(5.4,-2.4) J3(5,-2.4) J4(4.6,-2.4) J5(4.2,-2.4) J6(3.8,-2.4) J7(3.4,-2.4) J9(2.6,-2.4) J10(2.2,-2.4) J11(1.8,-2.4) J12(1.4,-2.4) J13(1,-2.4) J14(0.6,-2.4) J15(0.2,-2.4) J16(-0.2,-2.4) J17(-0.6,-2.4) J18(-1,-2.4) J19(-1.4,-2.4) J20(-1.8,-2.4) J22(-2.6,-2.4) J24(-3.4,-2.4) J25(-3.8,-2.4) J26(-4.2,-2.4) J27(-4.6,-2.4) J28(-5,-2.4) J29(-5.4,-2.4) J30(-5.8,-2.4) K1(5.8,-2) K2(5.4,-2) K3(5,-2) K4(4.6,-2) K5(4.2,-2) K6(3.8,-2) K7(3.4,-2) K8(3,-2) K10(2.2,-2) K11(1.8,-2) K12(1.4,-2) K13(1,-2) K14(0.6,-2) K15(0.2,-2) K16(-0.2,-2) K17(-0.6,-2) K18(-1,-2) K19(-1.4,-2) K20(-1.8,-2) K22(-2.6,-2) K24(-3.4,-2) K25(-3.8,-2) K26(-4.2,-2) K27(-4.6,-2) K28(-5,-2) K29(-5.4,-2) K30(-5.8,-2) L2(5.4,-1.6) L3(5,-1.6) L4(4.6,-1.6) L5(4.2,-1.6) L6(3.8,-1.6) L7(3.4,-1.6) L8(3,-1.6) L10(2.2,-1.6) L11(1.8,-1.6) L12(1.4,-1.6) L13(1,-1.6) L14(0.6,-1.6) L15(0.2,-1.6) L16(-0.2,-1.6) L17(-0.6,-1.6) L18(-1,-1.6) L19(-1.4,-1.6) L20(-1.8,-1.6) L24(-3.4,-1.6) L25(-3.8,-1.6) L26(-4.2,-1.6) L27(-4.6,-1.6) L28(-5,-1.6) L29(-5.4,-1.6) L30(-5.8,-1.6) M1(5.8,-1.2) M2(5.4,-1.2) M3(5,-1.2) M4(4.6,-1.2) M5(4.2,-1.2) M6(3.8,-1.2) M7(3.4,-1.2) M8(3,-1.2) M10(2.2,-1.2) M11(1.8,-1.2) M13(1,-1.2) M15(0.2,-1.2) M16(-0.2,-1.2) M17(-0.6,-1.2) M18(-1,-1.2) M19(-1.4,-1.2) M22(-2.6,-1.2) M23(-3,-1.2) M24(-3.4,-1.2) M25(-3.8,-1.2) M26(-4.2,-1.2) M27(-4.6,-1.2) M28(-5,-1.2) M29(-5.4,-1.2) M30(-5.8,-1.2) N1(5.8,-0.8) N2(5.4,-0.8) N3(5,-0.8) N4(4.6,-0.8) N5(4.2,-0.8) N7(3.4,-0.8) N8(3,-0.8) N9(2.6,-0.8) N11(1.8,-0.8) N13(1,-0.8) N15(0.2,-0.8) N17(-0.6,-0.8) N19(-1.4,-0.8) N20(-1.8,-0.8) N21(-2.2,-0.8) N24(-3.4,-0.8) N25(-3.8,-0.8) N26(-4.2,-0.8) N27(-4.6,-0.8) N28(-5,-0.8) N29(-5.4,-0.8) P2(5.4,-0.4) P3(5,-0.4) P4(4.6,-0.4) P5(4.2,-0.4) P6(3.8,-0.4) P7(3.4,-0.4) P8(3,-0.4) P10(2.2,-0.4) P11(1.8,-0.4) P12(1.4,-0.4) P13(1,-0.4) P14(0.6,-0.4) P15(0.2,-0.4) P17(-0.6,-0.4) P18(-1,-0.4) P19(-1.4,-0.4) P23(-3,-0.4) P24(-3.4,-0.4) P25(-3.8,-0.4) P26(-4.2,-0.4) P27(-4.6,-0.4) P28(-5,-0.4) P29(-5.4,-0.4) P30(-5.8,-0.4) R1(5.8,0) R2(5.4,0) R3(5,0) R4(4.6,0) R5(4.2,0) R6(3.8,0) R7(3.4,0) R9(2.6,0) R10(2.2,0) R11(1.8,0) R12(1.4,0) R13(1,0) R15(0.2,0) R16(-0.2,0) R17(-0.6,0) R19(-1.4,0) R20(-1.8,0) R22(-2.6,0) R23(-3,0) R25(-3.8,0) R27(-4.6,0) R28(-5,0) R29(-5.4,0) R30(-5.8,0) T1(5.8,0.4) T2(5.4,0.4) T3(5,0.4) T4(4.6,0.4) T5(4.2,0.4) T6(3.8,0.4) T7(3.4,0.4) T9(2.6,0.4) T10(2.2,0.4) T11(1.8,0.4) T13(1,0.4) T15(0.2,0.4) T17(-0.6,0.4) T19(-1.4,0.4) T20(-1.8,0.4) T22(-2.6,0.4) T23(-3,0.4) T25(-3.8,0.4) T26(-4.2,0.4) T27(-4.6,0.4) T28(-5,0.4) T29(-5.4,0.4) T30(-5.8,0.4) U2(5.4,0.8) U3(5,0.8) U4(4.6,0.8) U5(4.2,0.8) U6(3.8,0.8) U7(3.4,0.8) U10(2.2,0.8) U11(1.8,0.8) U13(1,0.8) U15(0.2,0.8) U17(-0.6,0.8) U19(-1.4,0.8) U20(-1.8,0.8) U21(-2.2,0.8) U22(-2.6,0.8) U23(-3,0.8) U26(-4.2,0.8) U27(-4.6,0.8) U28(-5,0.8) U29(-5.4,0.8) V1(5.8,1.2) V2(5.4,1.2) V3(5,1.2) V4(4.6,1.2) V5(4.2,1.2) V6(3.8,1.2) V7(3.4,1.2) V8(3,1.2) V9(2.6,1.2) V10(2.2,1.2) V11(1.8,1.2) V12(1.4,1.2) V13(1,1.2) V14(0.6,1.2) V15(0.2,1.2) V16(-0.2,1.2) V17(-0.6,1.2) V18(-1,1.2) V19(-1.4,1.2) V21(-2.2,1.2) V23(-3,1.2) V24(-3.4,1.2) V26(-4.2,1.2) V27(-4.6,1.2) V28(-5,1.2) V29(-5.4,1.2) V30(-5.8,1.2) W1(5.8,1.6) W2(5.4,1.6) W3(5,1.6) W4(4.6,1.6) W5(4.2,1.6) W6(3.8,1.6) W9(2.6,1.6) W10(2.2,1.6) W11(1.8,1.6) W13(1,1.6) W14(0.6,1.6) W16(-0.2,1.6) W17(-0.6,1.6) W18(-1,1.6) W19(-1.4,1.6) W20(-1.8,1.6) W21(-2.2,1.6) W22(-2.6,1.6) W23(-3,1.6) W24(-3.4,1.6) W26(-4.2,1.6) W27(-4.6,1.6) W28(-5,1.6) W29(-5.4,1.6) W30(-5.8,1.6) Y2(5.4,2) Y3(5,2) Y4(4.6,2) Y5(4.2,2) Y6(3.8,2) Y8(3,2) Y9(2.6,2) Y10(2.2,2) Y11(1.8,2) Y12(1.4,2) Y13(1,2) Y15(0.2,2) Y16(-0.2,2) Y17(-0.6,2) Y18(-1,2) Y19(-1.4,2) Y20(-1.8,2) Y21(-2.2,2) Y22(-2.6,2) Y23(-3,2) Y24(-3.4,2) Y26(-4.2,2) Y27(-4.6,2) Y28(-5,2) Y29(-5.4,2)
C0201_H04_T30
  rect 0.381x0.305 smd: 1(0,0.252) 2(0,-0.252)
C0201_H030
  rect 0.305x0.305 smd: 1(0,0.254) 2(0,-0.254)
C0201_H040
  rect 0.305x0.305 smd: 1(0,0.254) 2(0,-0.254)
C0201_H060
  rect 0.305x0.305 smd: 1(0,0.254) 2(0,-0.254)
C0402_H07_T30
  rect 0.65x0.56 smd: 1(0,0.48) 2(0,-0.48)
C0402_H060
  rect 0.559x0.559 smd: 1(0,0.483) 2(0,-0.483)
C0603_H090
  rect 0.95x0.75 smd: 1(0,0.75) 2(0,-0.75)
C0603_H100
  rect 0.95x0.75 smd: 1(0,0.75) 2(0,-0.75)
C0805_H150
  rect 1.524x0.9 smd: 1(0,0.832) 2(0,-0.832)
CHOKE_60X59_H45_INPAQ
  rect 5.7x1.6 smd: 1(0,2.35) 2(0,-2.35)
CHOKE_200X160_H100_A
  rect 1.7x0.85 smd: 1(0,0.875) 2(0,-0.875)
D_06X03_H04_INPAQ
  rect 0.3x0.25 smd: 1(0,-0.2) 2(0,0.2)
D_06X03_H030_TOSHIBA
  rect 0.32x0.21 smd: 1(0,0.2) 2(0,-0.2)
DFN6P_16_PAD13X05_05H070P13X045
  rect 0.53x0.3 smd: 1(0.735,-0.5) 2(0.735,0) 3(0.735,0.5) 4(-0.735,0.5) 5(-0.735,0) 6(-0.735,-0.5)
  rect 0.45x1.3 smd: 7(0,0)
DFN6P_16X10_05_H070
  rect 0.675x0.2 smd: 1(0.438,-0.5) 2(0.438,0) 5(-0.438,0) 6(-0.438,-0.5)
  rect 0.775x0.4 smd: 3(0.388,0.5) 4(-0.388,0.5)
DFN10P_25X10_05_H070_SE
  rect 0.675x0.2 smd: 1(0.438,-1) 2(0.438,-0.5) 4(0.438,0.5) 5(0.438,1) 6(-0.438,1) 7(-0.438,0.5) 9(-0.438,-0.5) 10(-0.438,-1)
  rect 0.675x0.4 smd: 3(0.438,0)
  rect 1.55x0.4 smd: 8(0,0)
DFN12_30_0D5_H08_P25X13_DRR
  rect 0.62x0.3 smd: 1(1.39,-1.25) 2(1.39,-0.75) 3(1.39,-0.25) 4(1.39,0.25) 5(1.39,0.75) 6(1.39,1.25) 7(-1.39,1.25) 8(-1.39,0.75) 9(-1.39,0.25) 10(-1.39,-0.25) 11(-1.39,-0.75) 12(-1.39,-1.25)
  rect 1.3x2.5 smd: 13(0,0)
HEAD2X3_76X50_2D54_H87_M_PIP
  round 1.96 hole 1.21: 1(0,0) 2(0,2.54) 3(2.54,0) 4(2.54,2.54) 5(5.08,0) 6(5.08,2.54)
HEAD2X5P_127X62_254_H970_M
  rect 3.11x1 smd: 1(2.185,-5.08) 2(-2.185,-5.08) 3(2.185,-2.54) 4(-2.185,-2.54) 5(2.185,0) 6(-2.185,0) 7(2.185,2.54) 8(-2.185,2.54) 9(2.185,5.08) 10(-2.185,5.08)
HEAD2X30_385X50_1D27_H48_F_R_P
  round 0.8 hole 0.8 unplated: (0,-17.78) (0,17.78)
  rect 1.7x0.65 smd: 1(1.95,-18.415) 2(-1.95,-18.415) 3(1.95,-17.145) 4(-1.95,-17.145) 5(1.95,-15.875) 6(-1.95,-15.875) 7(1.95,-14.605) 8(-1.95,-14.605) 9(1.95,-13.335) 10(-1.95,-13.335) 11(1.95,-12.065) 12(-1.95,-12.065) 13(1.95,-10.795) 14(-1.95,-10.795) 15(1.95,-9.525) 16(-1.95,-9.525) 17(1.95,-8.255) 18(-1.95,-8.255) 19(1.95,-6.985) 20(-1.95,-6.985) 21(1.95,-5.715) 22(-1.95,-5.715) 23(1.95,-4.445) 24(-1.95,-4.445) 25(1.95,-3.175) 26(-1.95,-3.175) 27(1.95,-1.905) 28(-1.95,-1.905) 29(1.95,-0.635) 30(-1.95,-0.635) 31(1.95,0.635) 32(-1.95,0.635) 33(1.95,1.905) 34(-1.95,1.905) 35(1.95,3.175) 36(-1.95,3.175) 37(1.95,4.445) 38(-1.95,4.445) 39(1.95,5.715) 40(-1.95,5.715) 41(1.95,6.985) 42(-1.95,6.985) 43(1.95,8.255) 44(-1.95,8.255) 45(1.95,9.525) 46(-1.95,9.525) 47(1.95,10.795) 48(-1.95,10.795) 49(1.95,12.065) 50(-1.95,12.065) 51(1.95,13.335) 52(-1.95,13.335) 53(1.95,14.605) 54(-1.95,14.605) 55(1.95,15.875) 56(-1.95,15.875) 57(1.95,17.145) 58(-1.95,17.145) 59(1.95,18.415) 60(-1.95,18.415)
HEAD14_387X25_2D54_H87_F
  round 1.8 hole 1.05: 1(0,0) 2(2.54,0) 3(5.08,0) 4(7.62,0) 5(10.16,0) 6(12.7,0) 7(15.24,0) 8(17.78,0) 9(22.86,0) 10(25.4,0) 11(27.94,0) 12(30.48,0) 13(33.02,0) 14(35.56,0)
HEAD18_477X25_2D54_H87_F
  round 1.8 hole 1.05: 1(0,0) 2(2.54,0) 3(5.08,0) 4(7.62,0) 5(10.16,0) 6(12.7,0) 7(15.24,0) 8(17.78,0) 9(21.84,0) 10(24.38,0) 11(26.92,0) 12(29.46,0) 13(32,0) 14(34.54,0) 15(37.08,0) 16(39.62,0) 17(42.16,0) 18(44.7,0)
L_25X20_H10_D
  rect 2.3x0.95 smd: 1(0,1.075) 2(0,-1.075)
LED4_10X10_A1_H04
  rect 0.45x0.45 smd: 1(0.425,-0.425) 2(-0.425,-0.425) 3(-0.425,0.425) 4(0.425,0.425)
LED0603_H050
  rect 0.8x0.8 smd: 1(0,0.8) 2(0,-0.8)
LED0603_H090
  rect 0.8x0.8 smd: 1(0,0.8) 2(0,-0.8)
MODULE51_160X120_1D1_H26_LITEON
  round 0.5 smd: 1(5.37,-6.6) 2(5.37,-5.5) 3(5.37,-4.4) 4(5.37,-3.3) 5(5.37,-2.2) 6(5.37,-1.1) 7(5.37,0) 8(5.37,1.1) 9(5.37,2.2) 10(5.37,3.3) 11(5.37,4.4) 12(5.37,5.5) 13(5.37,6.6) 14(3.87,7.42) 15(2.77,7.42) 16(1.67,7.42) 17(0.57,7.42) 18(-0.53,7.42) 19(-1.63,7.42) 20(-2.73,7.42) 21(-3.83,7.42) 22(-5.42,6.6) 23(-5.42,5.5) 24(-5.42,4.4) 25(-5.42,3.3) 26(-5.42,2.2) 27(-5.42,1.1) 28(-5.42,0) 29(-5.42,-1.1) 30(-5.42,-2.2) 31(-5.42,-3.3) 32(-5.42,-4.4) 33(-5.42,-5.5) 34(-5.42,-6.6) 35(-3.83,-7.42) 36(-2.73,-7.42) 37(-1.63,-7.42) 38(-0.53,-7.42) 39(0.57,-7.42) 40(1.67,-7.42) 41(2.77,-7.42) 42(3.87,-7.42)
  round 0.94 smd: 43(0.59,0.43) 44(-0.61,0.43) 45(-1.81,0.43) 46(0.59,1.63) 47(-0.61,1.63) 48(-1.81,1.63) 49(0.59,2.83) 50(-0.61,2.83) 51(-1.81,2.83)
QFN12P_20X17_04_H060
  custom 0.075x0.075 smd: 1(0.7,-0.8)
  rect 0.7x0.2 smd: 2(0.7,-0.4) 3(0.7,0) 4(0.7,0.4) 5(0.7,0.8) 7(-0.7,0.8) 8(-0.7,0.4) 9(-0.7,0) 10(-0.7,-0.4) 11(-0.7,-0.8)
  rect 0.2x0.7 smd: 6(0,0.85) 12(0,-0.85)
R0201_H030
  rect 0.305x0.305 smd: 1(0,0.254) 2(0,-0.254)
R0402_H040
  rect 0.559x0.559 smd: 1(0,0.483) 2(0,-0.483)
R0603_H060
  rect 0.95x0.75 smd: 1(0,0.75) 2(0,-0.75)
R1206_H080
  rect 1.7x1.1 smd: 1(0,1.45) 2(0,-1.45)
SB0201#2
  rect 0.305x0.305 smd: 1(0,0.267)
  rect 0.305x0.559 smd: 2(0,-0.14)
SMA_H240
  rect 1.7x2 smd: 1(0,2.05) 2(0,-2.05)
SOD323FL_H090_UM
  rect 0.44x0.74 smd: 1(0,1.15) 2(0,-1.15)
SOT23_5P_29X28_H150
  rect 1.15x0.6 smd: 1(-1.225,0.95) 2(-1.225,0) 3(-1.225,-0.95) 4(1.225,-0.95) 5(1.225,0.95)
SOT23_6P_29X28_H110
  rect 1.15x0.6 smd: 1(1.225,-0.95) 2(1.225,0) 3(1.225,0.95) 4(-1.225,0.95) 5(-1.225,0) 6(-1.225,-0.95)
SOT23_6P_29X28_H150
  rect 1.15x0.6 smd: 1(1.225,-0.95) 2(1.225,0) 3(1.225,0.95) 4(-1.225,0.95) 5(-1.225,0) 6(-1.225,-0.95)
SOT23_29X24_H110
  rect 1.15x0.6 smd: 1(1.025,-0.95) 2(1.025,0.95) 3(-1.025,0)
SOT323_21X20_H110
  rect 0.9x0.4 smd: 1(0.9,-0.65) 2(0.9,0.65) 3(-0.9,0)
SOT363_6P_21X20_H110
  rect 0.9x0.4 smd: 1(0.9,-0.65) 2(0.9,0) 3(0.9,0.65) 4(-0.9,0.65) 5(-0.9,0) 6(-0.9,-0.65)
SOT363_6P_22X21_H110
  rect 0.9x0.4 smd: 1(0.9,-0.65) 2(0.9,0) 3(0.9,0.65) 4(-0.9,0.65) 5(-0.9,0) 6(-0.9,-0.65)
SW5_85X64_H34_P12
  rect 1.2x1.3 smd: 1(4.2,-2.25) 2(-4.2,-2.25) 3(4.2,2.25) 4(-4.2,2.25)
  rect 1.2x1.4 smd: 5(4.2,0)
TP20MIL
  round 0.508 smd: 1(0,0)
TP32MIL_OSP
  round 0.813 smd: 1(0,0)
TP40MIL
  round 1.016 smd: 1(0,0)
TRES0201_H030
  rect 0.305x0.305 smd: 1(0,0.254) 2(0,-0.254)
unnamed#2
  round 0.8 smd: (0,0)
USB2X12_89X81_H35
  round 0.5 hole 0.5 unplated: (1.85,3.4) (1.85,-3.4)
  rect 0.95x0.27 smd: A1(3.825,2.625) A2(3.825,2.125) A3(3.825,1.625) A4(3.825,1.125) A5(3.825,0.625) A6(3.825,0.125) A7(3.825,-0.375) A8(3.825,-0.875) A9(3.825,-1.375) A10(3.825,-1.875) A11(3.825,-2.375) A12(3.825,-2.875) B1(2.525,-2.625) B2(2.525,-2.125) B3(2.525,-1.625) B4(2.525,-1.125) B5(2.525,-0.625) B6(2.525,-0.125) B7(2.525,0.375) B8(2.525,0.875) B9(2.525,1.375) B10(2.525,1.875) B11(2.525,2.375) B12(2.525,2.875)
  oval 2.1x1 hole 1.7x0.6: S1(3.2,4.32) S2(3.2,-4.32)
  oval 1.1x1.4 hole 0.7x1.2: S3(2.7,4.02) S4(2.7,-4.02)
  oval 2.7x1.2 hole 2.1x0.6: S5(-1.35,4.32) S6(-1.35,-4.32)
WTB4_60X51_1_H32_D90
  rect 1.55x0.6 smd: 1(2.05,1.5) 2(2.05,0.5) 3(2.05,-0.5) 4(2.05,-1.5)
  rect 1.8x1.2 smd: 5(-1.825,2.8) 6(-1.825,-2.8)
XTAL2P_32X15_H090
  rect 1.65x1.25 smd: 1(0,1.4) 2(0,-1.4)
XTAL4P_16X12_H070_TXC
  custom 0.138x0.138 smd: 1(0.425,-0.625) 2(0.425,0.625) 3(-0.425,0.625) 4(-0.425,-0.625)
XTAL4P_32X25_H080
  rect 1.2x1.4 smd: 1(0.85,-1.1) 2(0.85,1.1) 3(-0.85,1.1) 4(-0.85,-1.1)
XTAL4P_32X25_H080_HOSONIC
  rect 1.2x1.4 smd: 1(0.8,-1.1) 2(0.8,1.1) 3(-0.8,1.1) 4(-0.8,-1.1)

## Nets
5V_BUCK_BOOT: C2813.2 U2803.4
5V_BUCK_C: C2810.2 C2811.1
5V_BUCK_EN: R2811.2 R2812.1 U2803.9
5V_BUCK_FB: C2814.2 R2814.2 R2815.1 U2803.7
5V_BUCK_FB_C: C2814.1 R2816.2
5V_BUCK_OUT: C2815.1 C2816.1 D2803.1 L2803.2 R2814.1 R2816.1
5V_BUCK_RT: R2813.1 U2803.6
5V_BUCK_SW: C2813.1 L2803.1 U2803.1 U2803.2 U2803.3
5V_BUCK_VIN: C2810.1 C2812.1 D2802.2(CATHODE) R2811.1 U2803.10 U2803.11 U2803.12(VIN#12)
5V_SYS: C2611.1 C2617.1 C2621.1 C2622.1 C2801.1 C2802.1 D2801.2(CATHODE) D2803.2(CATHODE) D26017.2 D26097.2 JANALOG1.5 JMISC1.54 JMISC1.56 JSPI1.2 Q2801.2(S) R2801.1 R2809.1 U2801.4(VIN)
5V_USB_VBUS: C2607.1 C2608.1 D2801.1 JUSB1.A4 JUSB1.A9 JUSB1.B4 JUSB1.B9(VBUS#B9) U2604.6(VBUS#6)
5V_USB_VBUS_ON_N: Q2801.1 Q2802.3 R2809.2
AVDD1P0V: C3010.1 C3011.1 C3012.1 R3011.2 U3001.A4 U3001.C5 U3001.C6 U3001.F5
AVDD1P8V: C3007.1 C3008.1 C3009.1 R3010.2 R3024.1 U3001.E3 U3001.F3
AVDD3P0V: C3001.1 C3002.1 C3003.1 C3026.1 U3001.C4 U3004.5(OUT)
DVDD1P0V: C3004.1 C3005.1 C3006.1 R3009.2 U3001.D6 U3001.E5 U3001.E6
DVDD1P8V: C3013.1 C3014.1 C3015.1 R3012.2 R3022.1 R3023.1 R3025.1 R3026.1 R3027.1 U3001.F4
GND: ANT1.2 C502.2 C503.2 C504.2 C505.2 C506.2 C507.2 C508.2 C509.2 C510.2 C511.2 C512.2 C601.2 C602.2 C603.2 C604.2 C605.2 C606.2 C607.2 C608.2 C610.2 C701.2 C702.2 C704.2 C705.2 C706.2 C707.2 C708.2 C709.2 C710.2 C711.2 C712.2 C713.2 C714.2 C715.2 C716.2 C717.2 C718.2 C719.2 C721.2 C801.2 C802.2 C803.2 C804.2 C805.2 C806.2 C807.2 C808.2 C809.2 C810.2 C811.2 C812.2 C813.2 C814.2 C815.2 C816.2 C817.2 C818.2 C819.2 C820.2 C821.2 C822.2 C823.2 C824.2 C825.2 C826.2 C827.2 C828.2 C829.2 C830.2 C831.2 C832.2 C901.2 C902.2 C1001.2 C1002.2 C1003.2 C1004.2 C1005.2 C1006.2 C1007.2 C1008.2 C1009.2 C1010.2 C1011.2 C1012.2 C1101.2 C1102.2 C1103.2 C1104.2 C1105.2 C1106.2 C1201.2 C1202.2 C1203.2 C1601.2 C1602.2 C1603.2 C1604.2 C1701.2 C1702.2 C1703.2 C1704.2 C1705.2 C1706.2 C1707.2 C1708.2 C1709.2 C1710.2 C1711.2 C1712.2 C1713.2 C1714.2 C1715.2 C1716.2 C1717.2 C1718.2 C1719.2 C1720.2 C1721.2 C1722.2 C1723.2 C1724.2 C1725.2 C1727.2 C1728.2 C1729.2 C1730.2 C1731.2 C1732.2 C1733.2 C1734.2 C1735.2 C1736.2 C1737.2 C1738.2 C1739.2 C1740.2 C1741.2 C1742.2 C1743.2 C1801.2 C1802.2 C1803.2 C1804.2 C1805.2 C1806.2 C1807.2 C1808.2 C1809.2 C1810.2 C1811.2 C1812.2 C1813.2 C1814.2 C1815.2 C1816.2 C1817.2 C1818.2 C1819.2 C1820.2 C1821.2 C1822.2 C1823.2 C1824.2 C1825.2 C1826.2 C1827.2 C1828.2 C1829.2 C1830.2 C1831.2 C1833.2 C1834.2 C1835.2 C1836.2 C1837.2 C1838.2 C1839.2 C1840.2 C1841.2 C1842.2 C1843.2 C1844.2 C1845.2 C1846.2 C1847.2 C1848.2 C1849.2 C1850.2 C1851.2 C1901.2 C1902.2 C1903.2 C1904.2 C1905.2 C1906.2 C1907.2 C1908.2 C1909.2 C1910.2 C1911.2 C1912.2 C1913.2 C1914.2 C1915.2 C1916.2 C1917.2 C1918.2 C1919.2 C1920.2 C1921.2 C1922.2 C1923.2 C1924.2 C1925.2 C1926.2 C1927.2 C1928.2 C1929.2 C1930.2 C1931.2 C1932.2 C1933.2 C1934.2 C1935.2 C1936.2 C1937.2 C1938.2 C1939.2 C1940.2 C2101.2 C2102.2 C2103.2 C2104.2 C2105.2 C2106.2 C2107.2 C2201.2 C2202.2 C2203.2 C2204.2 C2205.2 C2206.2 C2207.2 C2208.2 C2209.2 C2210.2 C2211.2 C2212.2 C2213.2 C2214.2 C2215.2 C2216.2 C2217.2 C2218.2 C2219.2 C2220.2 C2501.2 C2502.2 C2503.2 C2504.2 C2505.2 C2506.2 C2507.2 C2508.2 C2509.2 C2510.2 C2511.2 C2512.2 C2513.2 C2514.2 C2515.2 C2516.2 C2517.2 C2518.2 C2519.2 C2520.2 C2521.2 C2522.2 C2523.2 C2524.2 C2525.2 C2526.2 C2527.2 C2528.2 C2529.2 C2605.2 C2607.2 C2608.2 C2609.2 C2610.2 C2611.2 C2614.2 C2615.2 C2616.2 C2617.2 C2618.2 C2619.2 C2620.2 C2621.2 C2622.2 C2623.2 C2624.2 C2625.2 C2626.2 C2631.2 C2632.2 C2633.2 C2701.2 C2702.2 C2703.2 C2704.2 C2705.2 C2706.2 C2801.2 C2802.2 C2804.2 C2805.2 C2806.2 C2808.2 C2809.2 C2811.2 C2812.2 C2815.2 C2816.2 C2901.2 C2907.2 C2909.2 C2911.2 C2912.2 C2921.2 C2922.2 C2923.2 C2924.2 C3001.2 C3002.2 C3003.2 C3004.2 C3005.2 C3006.2 C3007.2 C3008.2 C3009.2 C3010.2 C3011.2 C3012.2 C3013.2 C3014.2 C3015.2 C3016.2 C3017.2 C3018.2 C3021.2 C3022.2 C3025.2 C3026.2 C3027.2 C3028.2 D26001.1 D26002.1 D26003.1 D26005.1 D26006.1 D26007.1 D26008.1 D26009.1 D26017.1 D26046.1 D26047.1 D26048.1 D26049.1 D26050.1 D26051.1 D26063.1 D26064.1 D26065.1 D26066.1 D26067.1 D26069.1 D26070.1 D26071.1 D26072.1 D26073.1 D26074.1 D26075.1 D26076.1 D26087.1 D26088.1 D26089.1 D26090.1 D26091.1 D26092.1 D26093.1 D26094.1 D26097.1 D26099.1 D26100.1 D26101.1 D26102.1 D26103.1 D26104.1 D26105.1 D26201.1 D27201.2(CATHODE) DRAM1.A3 DRAM1.A10 DRAM1.AB3 DRAM1.AB5 DRAM1.AB8 DRAM1.AB10 DRAM1.C1 DRAM1.C5 DRAM1.C8 DRAM1.C12 DRAM1.D2 DRAM1.D4 DRAM1.D9 DRAM1.D11 DRAM1.E1 DRAM1.E5 DRAM1.E8 DRAM1.E12 DRAM1.G1 DRAM1.G3 DRAM1.G5 DRAM1.G8 DRAM1.G10 DRAM1.G12 DRAM1.J1 DRAM1.J3 DRAM1.J10 DRAM1.J12 DRAM1.K2 DRAM1.K4 DRAM1.K9 DRAM1.K11 DRAM1.N2 DRAM1.N4 DRAM1.N9 DRAM1.N11 DRAM1.P1 DRAM1.P3 DRAM1.P10 DRAM1.P12 DRAM1.T1 DRAM1.T3 DRAM1.T5 DRAM1.T8 DRAM1.T10 DRAM1.T12 DRAM1.V1 DRAM1.V5 DRAM1.V8 DRAM1.V12 DRAM1.W2 DRAM1.W4 DRAM1.W9 DRAM1.W11 DRAM1.Y1 DRAM1.Y5 DRAM1.Y8 DRAM1.Y12(VSS_57) EMMC1.A6 EMMC1.C4 EMMC1.E7 EMMC1.G5 EMMC1.H10 EMMC1.J5 EMMC1.K8 EMMC1.N2 EMMC1.N5 EMMC1.P4 EMMC1.P6 JANALOG1.6 JANALOG1.7 JBTN1.3 JBTN1.4 JBTN1.5 JCTL1.1 JCTL1.7 JDIGITAL1.15 JMEDIA1.1 JMEDIA1.2 JMEDIA1.7 JMEDIA1.8 JMEDIA1.13 JMEDIA1.14 JMEDIA1.19 JMEDIA1.20 JMEDIA1.25 JMEDIA1.26 JMEDIA1.31 JMEDIA1.32 JMEDIA1.37 JMEDIA1.38 JMEDIA1.43 JMEDIA1.44 JMEDIA1.49 JMEDIA1.50 JMEDIA1.55 JMEDIA1.56 JMISC1.26 JMISC1.27 JMISC1.35 JMISC1.44 JMISC1.58 JSPI1.6 JUSB1.A1 JUSB1.A12 JUSB1.B1 JUSB1.B12 JUSB1.S1 JUSB1.S2 JUSB1.S3 JUSB1.S4 JUSB1.S5 JUSB1.S6 MCU1.B2 MCU1.B4 MCU1.B8 MCU1.B11 MCU1.E12(VSS_9) MCU1.F2 MCU1.H2 MCU1.J12 MCU1.K2 MCU1.M3 MCU1.M7 MCU1.M11 PMIC1.A3 PMIC1.A11 PMIC1.A19 PMIC1.B4 PMIC1.B24 PMIC1.C11 PMIC1.C19 PMIC1.E1 PMIC1.E23 PMIC1.F22 PMIC1.G1 PMIC1.H20 PMIC1.J13 PMIC1.J15 PMIC1.J17 PMIC1.J19 PMIC1.J21 PMIC1.K14 PMIC1.K16 PMIC1.K18 PMIC1.K20 PMIC1.L5 PMIC1.L13 PMIC1.L15 PMIC1.L17 PMIC1.L19 PMIC1.M12 PMIC1.M16 PMIC1.M18 PMIC1.P22 PMIC1.R21 PMIC1.V4 PMIC1.V26 PMIC1.W3 PMIC1.W7 PMIC1.W27 PMIC1.Y2 Q2707.1(E2) Q2707.4 Q2708.1(E2) Q2708.4 Q2709.1(E2) Q2709.4 Q2802.2(EMITTER) QWIIC1.1 R601.2 R604.2 R605.2 R606.2 R705.2 R707.2 R1202.2 R1203.2 R1208.2 R1304.2 R1306.2 R1308.2 R1310.2 R1312.2 R1314.2 R1316.2 R1318.2 R1320.2 R1522.2 R1601.2 R1602.1 R2113.2 R2515.2 R2621.2 R2660.2 R2661.2 R2664.2 R2665.2 R2803.2 R2806.2 R2810.2 R2812.2 R2813.2 R2815.2 R2909.1 R3001.2 R3002.2 R3020.2 RT701.2 RT1901.2 SOC1.A4 SOC1.A13 SOC1.A14 SOC1.A16 SOC1.A17 SOC1.A27 SOC1.AA6 SOC1.AA8 SOC1.AA9 SOC1.AA11 SOC1.AA12 SOC1.AA14 SOC1.AA16 SOC1.AA17 SOC1.AA18 SOC1.AA19 SOC1.AA20 SOC1.AB3 SOC1.AB7 SOC1.AB8 SOC1.AB9 SOC1.AB12 SOC1.AB13 SOC1.AB14 SOC1.AB22 SOC1.AB23 SOC1.AB24 SOC1.AB25 SOC1.AB26 SOC1.AC6 SOC1.AC7 SOC1.AC8 SOC1.AC9 SOC1.AC10 SOC1.AC11 SOC1.AC12 SOC1.AC13 SOC1.AC15 SOC1.AC16 SOC1.AC20 SOC1.AC21 SOC1.AC22 SOC1.AC24 SOC1.AC28 SOC1.AD3 SOC1.AD6 SOC1.AD7 SOC1.AD8 SOC1.AD9 SOC1.AD12 SOC1.AD14 SOC1.AD15 SOC1.AE7 SOC1.AE8 SOC1.AE9 SOC1.AE10 SOC1.AE11 SOC1.AE12 SOC1.AE15 SOC1.AE18 SOC1.AF7 SOC1.AF8 SOC1.AF9 SOC1.AF10 SOC1.AF11 SOC1.AF12 SOC1.AF15 SOC1.AF16 SOC1.AG3 SOC1.AG5 SOC1.AG7 SOC1.AG8 SOC1.AG9 SOC1.AG10 SOC1.AG11 SOC1.AG12 SOC1.AG13 SOC1.AG14 SOC1.AG15 SOC1.AG16 SOC1.AG17 SOC1.AG20 SOC1.AG22 SOC1.AG24 SOC1.AG26 SOC1.AG28 SOC1.B2 SOC1.B3 SOC1.B4 SOC1.B14 SOC1.B16 SOC1.B27 SOC1.C2 SOC1.C3 SOC1.C5 SOC1.C6 SOC1.C7 SOC1.C8 SOC1.C9 SOC1.C10 SOC1.C11 SOC1.C12 SOC1.C13 SOC1.C14 SOC1.C17 SOC1.C18 SOC1.C19 SOC1.C20 SOC1.C21 SOC1.C22 SOC1.C23 SOC1.C24 SOC1.C25 SOC1.C26 SOC1.D1 SOC1.D2 SOC1.D3 SOC1.D14 SOC1.D16 SOC1.D27 SOC1.E2 SOC1.E3 SOC1.E4 SOC1.E14 SOC1.E15 SOC1.E16 SOC1.E26 SOC1.E27 SOC1.F2 SOC1.F3 SOC1.F4 SOC1.F5 SOC1.F6 SOC1.F7 SOC1.F8 SOC1.F9 SOC1.F22 SOC1.F23 SOC1.F25 SOC1.F26 SOC1.F27 SOC1.F29 SOC1.G5 SOC1.G6 SOC1.G8 SOC1.G11 SOC1.G12 SOC1.G19 SOC1.G20 SOC1.G23 SOC1.G28 SOC1.H2 SOC1.H5 SOC1.H6 SOC1.H7 SOC1.H24 SOC1.H25 SOC1.H26 SOC1.H28 SOC1.J2 SOC1.J3 SOC1.J4 SOC1.J5 SOC1.J6 SOC1.J12 SOC1.J13 SOC1.J14 SOC1.J15 SOC1.J16 SOC1.J17 SOC1.J18 SOC1.J19 SOC1.J20 SOC1.J22 SOC1.J25 SOC1.J26 SOC1.J29 SOC1.K5 SOC1.K6 SOC1.K10 SOC1.K19 SOC1.K20 SOC1.K25 SOC1.K26 SOC1.K27 SOC1.L3 SOC1.L6 SOC1.L7 SOC1.L8 SOC1.L24 SOC1.L27 SOC1.L28 SOC1.L29 SOC1.M7 SOC1.M8 SOC1.M10 SOC1.M11 SOC1.M13 SOC1.M15 SOC1.M16 SOC1.M17 SOC1.M18 SOC1.M22 SOC1.M26 SOC1.N5 SOC1.N7 SOC1.N8 SOC1.N21 SOC1.N25 SOC1.N26 SOC1.P4 SOC1.P5 SOC1.P6 SOC1.P7 SOC1.P8 SOC1.P10 SOC1.P11 SOC1.P12 SOC1.P13 SOC1.P14 SOC1.P17 SOC1.P18 SOC1.P25 SOC1.P26 SOC1.P28 SOC1.R5 SOC1.R6 SOC1.R23 SOC1.R27 SOC1.R29 SOC1.T5 SOC1.T6 SOC1.T9 SOC1.T11 SOC1.T13 SOC1.T15 SOC1.T17 SOC1.T20 SOC1.T22 SOC1.T29 SOC1.U4 SOC1.U5 SOC1.U6 SOC1.U10 SOC1.U11 SOC1.U13 SOC1.U15 SOC1.U17 SOC1.U26 SOC1.U28 SOC1.V5 SOC1.V6 SOC1.V7 SOC1.V8 SOC1.V15 SOC1.V16 SOC1.V17 SOC1.V18 SOC1.V19 SOC1.V21 SOC1.V23 SOC1.V24 SOC1.V26 SOC1.V29 SOC1.W5 SOC1.W6 SOC1.W9 SOC1.W10 SOC1.W11 SOC1.W13 SOC1.W22 SOC1.W23 SOC1.W24 SOC1.W26 SOC1.W27 SOC1.Y4 SOC1.Y5 SOC1.Y6 SOC1.Y26 SOC1.Y27 U1101.6 U1102.2 U2501.2 U2601.3 U2601.8 U2602.3 U2602.8 U2604.7 U2605.3 U2605.8 U2606.3 U2606.8 U2607.3 U2607.4 U2608.3 U2608.8 U2609.3 U2609.8 U2610.3 U2610.8 U2611.3 U2611.8 U2612.3 U2612.8 U2801.2 U2802.2 U2802.5 U2803.8 U2803.13 U2901.1 U2901.3 U2901.8 U2901.12 U2901.16 U2901.20 U2901.22 U2901.25 U2901.28 U2901.31 U2901.34 U2901.40 U2901.42 U2901.43 U2901.44 U2901.45 U2901.46 U2901.47 U2901.48 U2901.49 U2901.50 U2901.51 U3001.D3 U3001.D4 U3001.D5 U3001.E4 U3004.2 Y2501.2 Y2501.4 Y3001.2 Y3001.4
VBAT: C607.1 C2626.1 D26101.2 JMISC1.60 PMIC1.N27 PMIC1.P26 PMIC1.R27 R603.2 R2807.2
VBAT_CONN_VSNS_P: PMIC1.R23 R603.1
VBUS_DIV8: R3019.2 R3020.1 U3001.E2
VBUS_POWER_SWITCH_DISABLE_N: JCTL1.10 SB2801.1
